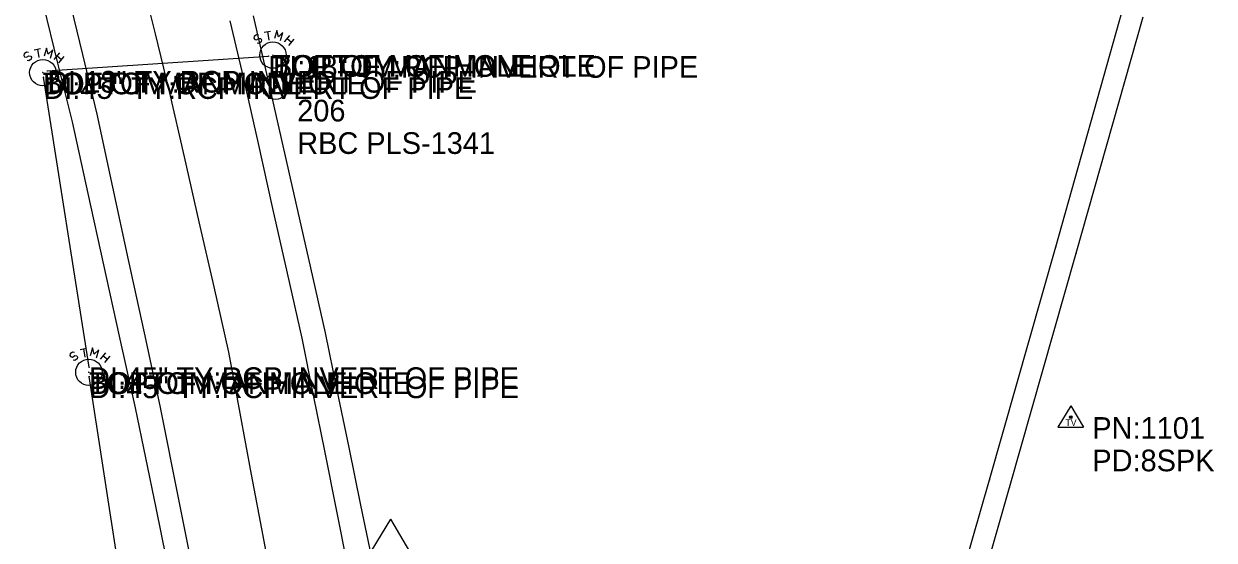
# Model space of a CAD drawing. Extents: x 929765 to 934279, y 1533086 to 1541189.
# Drawn here: x 931906.8 to 932181.9, y 1537774.2 to 1537893.4 of the extents above; entities that cross this region are included whole.
import ezdxf

# ---------------------------------------------------------------- set-up
doc = ezdxf.new("R2010")
doc.units = 0
for name, color, linetype in [('S_EDGE_PAVEMENT', 7, 'Continuous'), ('S_IRON_PIN', 7, 'Continuous'), ('S_IRON_PIN_ANNOT', 7, 'Continuous'), ('S_MANHOLE_ANNOT', 7, 'Continuous'), ('S_MSC_PT_SYM', 7, 'Continuous'), ('S_PAVEMENT_CROWN', 7, 'Continuous'), ('S_PRIMARY_CTL', 7, 'Continuous'), ('S_RAILROAD', 7, 'Continuous'), ('S_SECONDARY_CTL', 7, 'Continuous'), ('S_SECONDARY_CTL_ANNOT', 7, 'Continuous'), ('S_SHOULDER', 7, 'Continuous'), ('S_STORM_SEWER', 7, 'Continuous'), ('S_STORM_SEWER_ANNOT', 7, 'Continuous'), ('S_UTL_PT_SYM', 7, 'Continuous')]:
    doc.layers.add(name, color=color, linetype=linetype)

msp = doc.modelspace()

# ---------------------------------------------------------------- linework, layer by layer
at = {"layer": 'S_EDGE_PAVEMENT'}
for points in [[(931981.22, 1537534.96), (931979.16, 1537556.54), (931977.64, 1537570.72), (931975.6, 1537585.79), (931973.55, 1537600.86), (931971.51, 1537615.93), (931969.46, 1537631), (931966.94, 1537647.11), (931964.42, 1537663.22), (931961.89, 1537679.33), (931959.37, 1537695.44), (931956.33, 1537711.7), (931953.29, 1537727.95), (931950.25, 1537744.2), (931947.21, 1537760.45), (931942.74, 1537782.82), (931938.28, 1537805.2), (931934.64, 1537822.05), (931931, 1537838.9), (931927.36, 1537855.75), (931923.72, 1537872.6), (931920.41, 1537886.31), (931917.1, 1537900.03)], [(932013.54, 1537565.12), (932011.5, 1537579.83), (932009.47, 1537594.54), (932007.44, 1537609.25), (932005.4, 1537623.96), (932002.92, 1537640.28), (932000.43, 1537656.59), (931997.95, 1537672.9), (931995.46, 1537689.21), (931992.02, 1537708.93), (931988.58, 1537728.65), (931985.14, 1537748.37), (931981.7, 1537768.09), (931979.05, 1537781.28), (931976.4, 1537794.47), (931973.75, 1537807.66), (931971.1, 1537820.85), (931967.73, 1537835.84), (931964.36, 1537850.82), (931961, 1537865.81), (931957.63, 1537880.8), (931954.49, 1537894.12)]]:
    msp.add_lwpolyline(points, dxfattribs=at)
at = {"layer": 'S_IRON_PIN'}
for radius in [2.91, 0.411, 0.262, 0.212, 0.145, 0.0822, 0.0581]:
    msp.add_circle((931964.97, 1537878.89), radius, dxfattribs=at)
at = {"layer": 'S_MSC_PT_SYM'}
for points in [[(931963.31, 1537885.97), (931963.31, 1537886.02), (931963.31, 1537885.97), (931963.26, 1537885.97), (931963.31, 1537885.97), (931963.31, 1537885.92), (931963.31, 1537885.97), (931963.36, 1537885.97)], [(931911.33, 1537881.09), (931911.33, 1537881.14), (931911.33, 1537881.09), (931911.28, 1537881.09), (931911.33, 1537881.09), (931911.33, 1537881.04), (931911.33, 1537881.09), (931911.38, 1537881.09)], [(931912.19, 1537882.55), (931912.19, 1537882.6), (931912.19, 1537882.55), (931912.14, 1537882.55), (931912.19, 1537882.55), (931912.19, 1537882.5), (931912.19, 1537882.55), (931912.24, 1537882.55)], [(932145.29, 1537841.93), (932145.29, 1537841.98), (932145.29, 1537841.93), (932145.24, 1537841.93), (932145.29, 1537841.93), (932145.29, 1537841.88), (932145.29, 1537841.93), (932145.34, 1537841.93)], [(932150.02, 1537840.44), (932150.02, 1537840.49), (932150.02, 1537840.44), (932149.97, 1537840.44), (932150.02, 1537840.44), (932150.02, 1537840.39), (932150.02, 1537840.44), (932150.07, 1537840.44)], [(931921.85, 1537814.12), (931921.85, 1537814.17), (931921.85, 1537814.12), (931921.8, 1537814.12), (931921.85, 1537814.12), (931921.85, 1537814.07), (931921.85, 1537814.12), (931921.9, 1537814.12)], [(931921.9, 1537812), (931921.9, 1537812.05), (931921.9, 1537812), (931921.85, 1537812), (931921.9, 1537812), (931921.9, 1537811.95), (931921.9, 1537812), (931921.95, 1537812)], [(932129.95, 1537788.14), (932129.95, 1537788.19), (932129.95, 1537788.14), (932129.9, 1537788.14), (932129.95, 1537788.14), (932129.95, 1537788.09), (932129.95, 1537788.14), (932130, 1537788.14)], [(932134.58, 1537786.4), (932134.58, 1537786.45), (932134.58, 1537786.4), (932134.53, 1537786.4), (932134.58, 1537786.4), (932134.58, 1537786.35), (932134.58, 1537786.4), (932134.63, 1537786.4)]]:
    msp.add_lwpolyline(points, dxfattribs=at)
at = {"layer": 'S_PAVEMENT_CROWN'}
msp.add_lwpolyline([(931964.71, 1537761.1), (931962.08, 1537775.23), (931959.43, 1537789.37), (931956.79, 1537803.5), (931954.15, 1537817.63), (931950.74, 1537832.67), (931947.32, 1537847.71), (931943.9, 1537862.74), (931940.48, 1537877.78), (931937.21, 1537891.11), (931933.93, 1537904.45)], dxfattribs=at)
at = {"layer": 'S_PRIMARY_CTL'}
for q in [(931981.47, 1537762.56), (932001.33, 1537762.56)]:
    msp.add_line((931991.5, 1537779.07), q, dxfattribs=at)
at = {"layer": 'S_RAILROAD'}
for p, q in [((932145.29, 1537841.93), (932160.83, 1537896.91)), ((932150.02, 1537840.44), (932165.49, 1537895.04)), ((932129.95, 1537788.14), (932145.29, 1537841.93)), ((932134.58, 1537786.4), (932150.02, 1537840.44)), ((932114.55, 1537734.1), (932129.95, 1537788.14)), ((932119.29, 1537732.65), (932134.58, 1537786.4))]:
    msp.add_line(p, q, dxfattribs=at)
at = {"layer": 'S_SECONDARY_CTL'}
for p, q in [((932148.75, 1537805.22), (932145.74, 1537800.27)), ((932148.75, 1537805.22), (932151.69, 1537800.27)), ((932145.74, 1537800.27), (932151.69, 1537800.27))]:
    msp.add_line(p, q, dxfattribs=at)
for radius in [0.311, 0.183, 0.103]:
    msp.add_circle((932148.75, 1537802.61), radius, dxfattribs=at)
at = {"layer": 'S_SHOULDER'}
for points in [[(931973.95, 1537555.3), (931972.29, 1537569.03), (931970.18, 1537584.34), (931968.08, 1537599.65), (931965.97, 1537614.96), (931963.87, 1537630.27), (931961.31, 1537646.59), (931958.75, 1537662.9), (931956.19, 1537679.22), (931953.63, 1537695.53), (931950.75, 1537711.28), (931947.86, 1537727.03), (931944.98, 1537742.78), (931942.1, 1537758.53), (931937.34, 1537781.66), (931932.57, 1537804.8), (931928.93, 1537821.29), (931925.29, 1537837.78), (931921.65, 1537854.27), (931918.01, 1537870.76), (931914.67, 1537884.32), (931911.34, 1537897.89)], [(932021.69, 1537555.26), (932019.48, 1537565.71), (932017.57, 1537580.47), (932015.65, 1537595.24), (932013.73, 1537610), (932011.81, 1537624.76), (932009.32, 1537640.96), (932006.84, 1537657.16), (932004.35, 1537673.35), (932001.86, 1537689.55), (931998.25, 1537709.42), (931994.64, 1537729.29), (931991.03, 1537749.16), (931987.42, 1537769.03), (931984.69, 1537782.3), (931981.96, 1537795.57), (931979.23, 1537808.84), (931976.5, 1537822.11), (931973.12, 1537837.06), (931969.73, 1537852), (931966.34, 1537866.94), (931962.96, 1537881.88), (931959.83, 1537895.3)]]:
    msp.add_lwpolyline(points, dxfattribs=at)
at = {"layer": 'S_STORM_SEWER'}
for p, q in [((931962.32, 1537891.47), (931963.83, 1537891.74)), ((931963.1, 1537891.62), (931963.45, 1537889.69)), ((931960.04, 1537890.5), (931959.96, 1537890.11)), ((931959.96, 1537890.11), (931960.15, 1537889.84)), ((931960.58, 1537890.89), (931960.04, 1537890.5)), ((931960.15, 1537889.84), (931960.58, 1537889.72)), ((931961, 1537890.81), (931960.58, 1537890.89)), ((931960.58, 1537889.72), (931961.12, 1537890.07)), ((931961.12, 1537888.91), (931960.73, 1537888.99)), ((931961.12, 1537890.07), (931961.59, 1537890)), ((931961.66, 1537889.3), (931961.12, 1537888.91)), ((931961.59, 1537890), (931961.74, 1537889.72)), ((931961.74, 1537889.72), (931961.66, 1537889.3)), ((931967.01, 1537889.26), (931968.25, 1537890.73)), ((931967.67, 1537890.03), (931968.64, 1537889.22)), ((931969.22, 1537889.92), (931967.98, 1537888.45)), ((931906.86, 1537886.46), (931906.78, 1537886.08)), ((931906.78, 1537886.08), (931906.97, 1537885.8)), ((931907.4, 1537886.85), (931906.86, 1537886.46)), ((931906.97, 1537885.8), (931907.4, 1537885.69)), ((931907.83, 1537886.77), (931907.4, 1537886.85)), ((931907.4, 1537885.69), (931907.94, 1537886.04)), ((931907.94, 1537886.04), (931908.41, 1537885.96)), ((931908.41, 1537885.96), (931908.56, 1537885.69)), ((931908.56, 1537885.69), (931908.48, 1537885.26)), ((931909.14, 1537887.43), (931910.65, 1537887.7)), ((931909.92, 1537887.59), (931910.27, 1537885.65)), ((931912.19, 1537882.55), (931963.31, 1537885.97)), ((931913.83, 1537885.22), (931915.07, 1537886.7)), ((931914.49, 1537886), (931915.46, 1537885.18)), ((931916.04, 1537885.88), (931914.8, 1537884.41)), ((931907.94, 1537884.87), (931907.55, 1537884.95)), ((931908.48, 1537885.26), (931907.94, 1537884.87)), ((931921.85, 1537814.12), (931911.33, 1537881.09)), ((931917.5, 1537817.26), (931917.42, 1537816.87)), ((931918.04, 1537817.65), (931917.5, 1537817.26)), ((931918.46, 1537817.57), (931918.04, 1537817.65)), ((931919.78, 1537818.23), (931921.29, 1537818.5)), ((931920.56, 1537818.38), (931920.91, 1537816.45)), ((931924.47, 1537816.02), (931925.71, 1537817.49)), ((931917.42, 1537816.87), (931917.61, 1537816.6)), ((931917.61, 1537816.6), (931918.04, 1537816.48)), ((931918.04, 1537816.48), (931918.58, 1537816.83)), ((931918.58, 1537815.67), (931918.19, 1537815.75)), ((931918.58, 1537816.83), (931919.05, 1537816.76)), ((931919.12, 1537816.06), (931918.58, 1537815.67)), ((931919.05, 1537816.76), (931919.2, 1537816.48)), ((931919.2, 1537816.48), (931919.12, 1537816.06)), ((931925.13, 1537816.79), (931926.1, 1537815.98)), ((931926.68, 1537816.68), (931925.44, 1537815.21)), ((931941.47, 1537685.23), (931921.9, 1537812))]:
    msp.add_line(p, q, dxfattribs=at)
for points in [[(931966.12, 1537889.57), (931966.66, 1537891.43), (931965.62, 1537890.42), (931965.23, 1537891.86), (931964.69, 1537890)], [(931912.94, 1537885.53), (931913.48, 1537887.39), (931912.44, 1537886.39), (931912.05, 1537887.82), (931911.51, 1537885.96)], [(931923.58, 1537816.33), (931924.12, 1537818.19), (931923.08, 1537817.18), (931922.69, 1537818.62), (931922.15, 1537816.76)]]:
    msp.add_lwpolyline(points, dxfattribs=at)
for centre in [(931964.36, 1537886.2), (931911.18, 1537882.16), (931921.82, 1537812.96)]:
    msp.add_circle(centre, 3.05, dxfattribs=at)
at = {"layer": 'S_UTL_PT_SYM'}
for points in [[(931963.31, 1537885.97), (931963.31, 1537886.02), (931963.31, 1537885.97), (931963.26, 1537885.97), (931963.31, 1537885.97), (931963.31, 1537885.92), (931963.31, 1537885.97), (931963.36, 1537885.97)], [(931964.36, 1537886.2), (931964.36, 1537886.25), (931964.36, 1537886.2), (931964.31, 1537886.2), (931964.36, 1537886.2), (931964.36, 1537886.15), (931964.36, 1537886.2), (931964.41, 1537886.2)], [(931911.18, 1537882.16), (931911.18, 1537882.21), (931911.18, 1537882.16), (931911.13, 1537882.16), (931911.18, 1537882.16), (931911.18, 1537882.11), (931911.18, 1537882.16), (931911.23, 1537882.16)], [(931911.33, 1537881.09), (931911.33, 1537881.14), (931911.33, 1537881.09), (931911.28, 1537881.09), (931911.33, 1537881.09), (931911.33, 1537881.04), (931911.33, 1537881.09), (931911.38, 1537881.09)], [(931912.19, 1537882.55), (931912.19, 1537882.6), (931912.19, 1537882.55), (931912.14, 1537882.55), (931912.19, 1537882.55), (931912.19, 1537882.5), (931912.19, 1537882.55), (931912.24, 1537882.55)], [(931921.85, 1537814.12), (931921.85, 1537814.17), (931921.85, 1537814.12), (931921.8, 1537814.12), (931921.85, 1537814.12), (931921.85, 1537814.07), (931921.85, 1537814.12), (931921.9, 1537814.12)], [(931921.82, 1537812.96), (931921.82, 1537813.01), (931921.82, 1537812.96), (931921.77, 1537812.96), (931921.82, 1537812.96), (931921.82, 1537812.91), (931921.82, 1537812.96), (931921.87, 1537812.96)], [(931921.9, 1537812), (931921.9, 1537812.05), (931921.9, 1537812), (931921.85, 1537812), (931921.9, 1537812), (931921.9, 1537811.95), (931921.9, 1537812), (931921.95, 1537812)]]:
    msp.add_lwpolyline(points, dxfattribs=at)

# ---------------------------------------------------------------- texts
at = {"layer": 'S_IRON_PIN_ANNOT'}
for s, p in [('206', (931969.97, 1537870.89)), ('RBC PLS-1341', (931969.97, 1537863.39))]:
    msp.add_text(s, height=5, dxfattribs=at).set_placement(p)
at = {"layer": 'S_MANHOLE_ANNOT'}
for p in [(931964.36, 1537881.2), (931911.18, 1537877.16), (931921.82, 1537807.96)]:
    msp.add_text('BOTTOM OF MANHOLE', height=5, dxfattribs=at).set_placement(p)
at = {"layer": 'S_SECONDARY_CTL'}
msp.add_text('TV', height=1.5, rotation=360, dxfattribs=at).set_placement((932147.54, 1537800.6))
at = {"layer": 'S_SECONDARY_CTL_ANNOT'}
for s, p in [('PN:1101', (932153.75, 1537797.61)), ('PD:8SPK', (932153.75, 1537790.11))]:
    msp.add_text(s, height=5, dxfattribs=at).set_placement(p)
at = {"layer": 'S_STORM_SEWER_ANNOT'}
for s, p in [('DI:18" TY:RCP INVERT OF PIPE', (931963.31, 1537880.97)), ('TOP OF MANHOLE', (931964.36, 1537881.2)), ('TOP OF MANHOLE', (931911.18, 1537877.16)), ('DI:45" TY:RCP INVERT OF PIPE', (931911.33, 1537876.09)), ('DI:18" TY:RCP INVERT OF PIPE', (931912.19, 1537877.55)), ('DI:45" TY:RCP INVERT OF PIPE', (931921.85, 1537809.12)), ('TOP OF MANHOLE', (931921.82, 1537807.96)), ('DI:45" TY:RCP INVERT OF PIPE', (931921.9, 1537807))]:
    msp.add_text(s, height=5, dxfattribs=at).set_placement(p)

doc.saveas('drawing.dxf')
